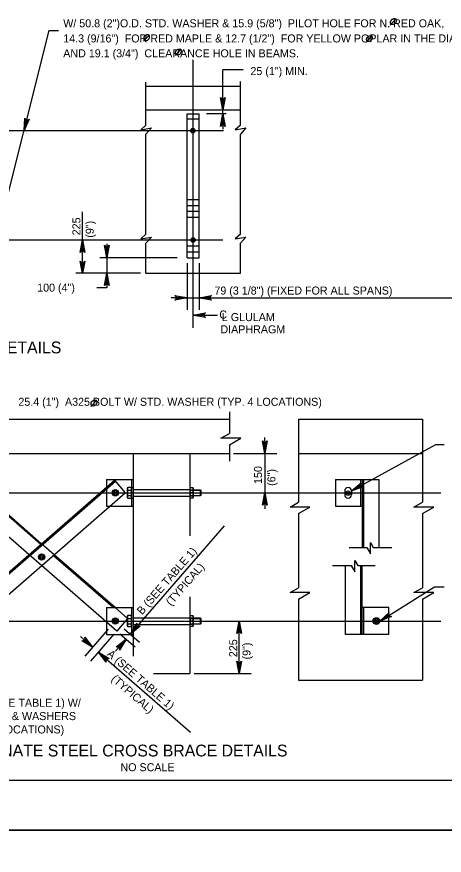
# Model space of a CAD drawing. Extents: x -13 to 81, y -176 to 0.
# Drawn here: x 41.37 to 47.78, y -44.38 to -31.81 of the extents above; entities that cross this region are included whole.
import ezdxf

# ---------------------------------------------------------------- set-up
doc = ezdxf.new("R2010")
doc.units = 0
for name, color, linetype in [('Level 1', 7, 'Continuous'), ('Level 3', 7, 'Continuous'), ('Level 4', 7, 'Continuous'), ('Level 5', 7, 'Continuous'), ('Level 63', 7, 'Continuous'), ('Level 7', 7, 'Continuous'), ('Level 8', 7, 'Continuous')]:
    doc.layers.add(name, color=color, linetype=linetype)

msp = doc.modelspace()

# ---------------------------------------------------------------- linework, layer by layer
at = {"layer": 'Level 1'}
msp.add_lwpolyline([(35.75, -43.25), (67.25, -43.25), (67.25, -22.75), (35.75, -22.75)], close=True, dxfattribs=at)
at = {"layer": 'Level 3'}
for p, q in [((41.07, -35.155), (41.862, -32.017)), ((41.862, -32.017), (41.998, -32.017)), ((44.018, -36.47), (44.018, -32.456)), ((44.767, -32.606), (44.464, -32.606)), ((44.514, -33.267), (44.22, -33.267)), ((37.386, -33.517), (44.475, -33.517)), ((42.361, -35.657), (42.361, -34.732)), ((37.386, -35.155), (44.465, -35.155)), ((42.726, -35.212), (42.726, -35.872)), ((43.777, -35.421), (42.62, -35.421)), ((43.231, -35.653), (42.259, -35.653)), ((42.726, -35.872), (42.577, -35.872)), ((44.018, -36.28), (44.382, -36.28)), ((45.093, -38.354), (45.093, -38.114)), ((44.562, -38.354), (44.562, -38.354)), ((44.624, -38.354), (45.273, -38.354)), ((45.093, -38.354), (45.093, -38.944)), ((44.562, -38.944), (44.562, -38.944)), ((44.624, -38.944), (45.273, -38.944)), ((45.093, -38.944), (45.093, -39.184)), ((45.093, -38.944), (45.093, -38.944)), ((42.718, -39.145), (42.771, -39.145)), ((42.771, -39.145), (43.121, -39.145)), ((43.971, -40.865), (43.971, -40.865)), ((44.034, -40.865), (44.89, -40.865)), ((44.71, -41.653), (44.71, -40.865)), ((44.71, -40.865), (44.71, -40.865)), ((43.971, -41.653), (43.971, -41.653)), ((44.034, -41.653), (44.89, -41.653))]:
    msp.add_line(p, q, dxfattribs=at)
for points in [[(41.483, -33.517), (41.495, -33.328), (41.501, -33.344), (41.511, -33.354), (41.523, -33.359), (41.535, -33.36), (41.549, -33.356), (41.562, -33.345), (41.483, -33.517), (41.549, -33.356), (41.535, -33.36), (41.483, -33.517), (41.523, -33.359), (41.511, -33.354), (41.483, -33.517), (41.501, -33.344)], [(42.361, -35.155), (42.396, -35.341), (42.386, -35.327), (42.374, -35.319), (42.361, -35.317), (42.349, -35.319), (42.336, -35.327), (42.326, -35.341), (42.361, -35.155), (42.336, -35.327), (42.349, -35.319), (42.361, -35.155), (42.361, -35.317), (42.374, -35.319), (42.361, -35.155), (42.386, -35.327)], [(42.726, -35.421), (42.691, -35.234), (42.701, -35.248), (42.713, -35.256), (42.726, -35.258), (42.738, -35.256), (42.751, -35.248), (42.761, -35.234), (42.726, -35.421), (42.751, -35.248), (42.738, -35.256), (42.726, -35.421), (42.726, -35.258), (42.713, -35.256), (42.726, -35.421), (42.701, -35.248)], [(42.361, -35.657), (42.326, -35.471), (42.336, -35.485), (42.349, -35.493), (42.361, -35.495), (42.374, -35.493), (42.386, -35.485), (42.396, -35.471), (42.361, -35.657), (42.386, -35.485), (42.374, -35.493), (42.361, -35.657), (42.361, -35.495), (42.349, -35.493), (42.361, -35.657), (42.336, -35.485)], [(42.726, -35.653), (42.761, -35.839), (42.751, -35.825), (42.738, -35.817), (42.726, -35.815), (42.713, -35.817), (42.701, -35.825), (42.691, -35.839), (42.726, -35.653), (42.701, -35.825), (42.713, -35.817), (42.726, -35.653), (42.726, -35.815), (42.738, -35.817), (42.726, -35.653), (42.751, -35.825)], [(43.929, -36.024), (43.743, -36.059), (43.757, -36.049), (43.765, -36.036), (43.767, -36.024), (43.765, -36.011), (43.757, -35.999), (43.743, -35.989), (43.929, -36.024), (43.757, -35.999), (43.765, -36.011), (43.929, -36.024), (43.767, -36.024), (43.765, -36.036), (43.929, -36.024), (43.757, -36.049)], [(44.107, -36.024), (44.293, -35.989), (44.279, -35.999), (44.271, -36.011), (44.269, -36.024), (44.271, -36.036), (44.279, -36.049), (44.293, -36.059), (44.107, -36.024), (44.279, -36.049), (44.271, -36.036), (44.107, -36.024), (44.269, -36.024), (44.271, -36.011), (44.107, -36.024), (44.279, -35.999)], [(44.018, -36.28), (44.204, -36.245), (44.19, -36.255), (44.183, -36.267), (44.181, -36.28), (44.183, -36.292), (44.19, -36.305), (44.204, -36.315), (44.018, -36.28), (44.19, -36.305), (44.183, -36.292), (44.018, -36.28), (44.181, -36.28), (44.183, -36.267), (44.018, -36.28), (44.19, -36.255)], [(45.093, -38.354), (45.058, -38.167), (45.067, -38.182), (45.08, -38.189), (45.093, -38.191), (45.105, -38.189), (45.117, -38.182), (45.127, -38.167), (45.093, -38.354), (45.117, -38.182), (45.105, -38.189), (45.093, -38.354), (45.093, -38.191), (45.08, -38.189), (45.093, -38.354), (45.067, -38.182)], [(46.392, -38.915), (47.656, -38.218), (47.784, -38.218)], [(45.093, -38.944), (45.127, -39.131), (45.117, -39.116), (45.105, -39.109), (45.093, -39.107), (45.08, -39.109), (45.067, -39.116), (45.057, -39.131), (45.093, -38.944), (45.067, -39.116), (45.08, -39.109), (45.093, -38.944), (45.093, -39.107), (45.105, -39.109), (45.093, -38.944), (45.117, -39.116)], [(46.817, -40.865), (47.64, -40.354), (47.784, -40.354)]]:
    msp.add_lwpolyline(points, dxfattribs=at)
at = {"layer": 'Level 4'}
for p, q in [((46.976, -31.935), (47.065, -31.837)), ((43.275, -32.177), (43.365, -32.079)), ((46.617, -32.191), (46.706, -32.092)), ((43.752, -32.391), (43.841, -32.293)), ((42.486, -37.652), (42.575, -37.554))]:
    msp.add_line(p, q, dxfattribs=at)
for points in [[(47.056, -31.846), (47.049, -31.841), (47.042, -31.839), (47.033, -31.838), (47.028, -31.838), (47.02, -31.84), (47.012, -31.844), (47.006, -31.847), (46.996, -31.855), (46.987, -31.866), (46.982, -31.876), (46.979, -31.886), (46.978, -31.894), (46.979, -31.901), (46.983, -31.912), (46.987, -31.918), (46.994, -31.923), (47.006, -31.926), (47.019, -31.926), (47.036, -31.918), (47.048, -31.908), (47.057, -31.895), (47.063, -31.882), (47.065, -31.867), (47.063, -31.857), (47.056, -31.846)], [(43.355, -32.088), (43.348, -32.083), (43.341, -32.081), (43.333, -32.08), (43.328, -32.08), (43.319, -32.082), (43.311, -32.086), (43.306, -32.089), (43.295, -32.097), (43.287, -32.108), (43.282, -32.118), (43.279, -32.127), (43.278, -32.136), (43.279, -32.143), (43.282, -32.154), (43.286, -32.159), (43.294, -32.165), (43.305, -32.168), (43.319, -32.168), (43.335, -32.16), (43.348, -32.15), (43.357, -32.137), (43.363, -32.124), (43.365, -32.109), (43.362, -32.099), (43.356, -32.088)], [(46.697, -32.102), (46.69, -32.097), (46.683, -32.095), (46.674, -32.094), (46.669, -32.094), (46.661, -32.096), (46.653, -32.1), (46.647, -32.103), (46.637, -32.111), (46.628, -32.122), (46.623, -32.132), (46.62, -32.141), (46.619, -32.15), (46.62, -32.157), (46.624, -32.168), (46.628, -32.173), (46.636, -32.179), (46.647, -32.182), (46.66, -32.181), (46.677, -32.174), (46.689, -32.163), (46.698, -32.151), (46.704, -32.137), (46.706, -32.123), (46.704, -32.113), (46.697, -32.102)], [(43.832, -32.303), (43.825, -32.297), (43.818, -32.295), (43.809, -32.294), (43.804, -32.294), (43.795, -32.296), (43.787, -32.3), (43.782, -32.303), (43.771, -32.312), (43.763, -32.322), (43.758, -32.332), (43.755, -32.342), (43.754, -32.35), (43.755, -32.358), (43.759, -32.368), (43.763, -32.374), (43.77, -32.38), (43.782, -32.382), (43.795, -32.382), (43.812, -32.374), (43.824, -32.364), (43.833, -32.351), (43.839, -32.338), (43.841, -32.323), (43.839, -32.314), (43.832, -32.303)], [(42.566, -37.563), (42.559, -37.558), (42.552, -37.556), (42.543, -37.555), (42.538, -37.555), (42.53, -37.557), (42.522, -37.561), (42.516, -37.564), (42.506, -37.573), (42.497, -37.583), (42.492, -37.593), (42.489, -37.603), (42.488, -37.611), (42.489, -37.619), (42.493, -37.629), (42.497, -37.635), (42.504, -37.641), (42.516, -37.643), (42.529, -37.643), (42.546, -37.635), (42.558, -37.625), (42.567, -37.612), (42.573, -37.599), (42.575, -37.584), (42.573, -37.575), (42.566, -37.563)]]:
    msp.add_spline(points, degree=3, dxfattribs=at)
at = {"layer": 'Level 5'}
for p, q in [((44.464, -32.979), (44.464, -32.606)), ((43.309, -33.436), (43.309, -32.79)), ((44.727, -33.436), (44.727, -32.781)), ((43.309, -32.852), (44.727, -32.852)), ((44.464, -33.267), (44.464, -32.979)), ((43.309, -33.206), (44.727, -33.206)), ((43.929, -35.421), (43.929, -33.267)), ((43.929, -33.267), (44.107, -33.267)), ((44.107, -35.421), (44.107, -33.267)), ((44.464, -33.267), (44.464, -33.494)), ((43.309, -33.436), (43.233, -33.505)), ((43.233, -33.505), (43.393, -33.477)), ((43.393, -33.477), (43.309, -33.568)), ((44.727, -33.436), (44.65, -33.505)), ((44.65, -33.505), (44.811, -33.477)), ((44.811, -33.477), (44.727, -33.568)), ((43.309, -35.069), (43.309, -33.568)), ((44.727, -35.069), (44.727, -33.568)), ((44.727, -34.796), (44.727, -33.568)), ((43.309, -35.069), (43.233, -35.139)), ((43.233, -35.139), (43.393, -35.111)), ((43.393, -35.111), (43.309, -35.201)), ((44.727, -35.069), (44.65, -35.139)), ((44.65, -35.139), (44.811, -35.111)), ((44.811, -35.111), (44.727, -35.201)), ((43.309, -35.653), (43.309, -35.201)), ((44.727, -35.653), (44.727, -35.201)), ((43.929, -35.421), (44.107, -35.421)), ((43.309, -35.653), (44.727, -35.653)), ((44.562, -37.731), (44.562, -38.053)), ((38.932, -37.842), (44.562, -37.842)), ((45.6, -37.842), (45.6, -39.084)), ((45.6, -37.842), (47.456, -37.842)), ((47.456, -37.842), (47.456, -39.084)), ((44.434, -38.127), (44.562, -38.053)), ((44.732, -38.127), (44.434, -38.127)), ((44.562, -38.225), (44.732, -38.127)), ((44.562, -38.225), (44.562, -38.47)), ((38.932, -38.354), (44.562, -38.354)), ((43.121, -38.354), (43.121, -41.391)), ((43.971, -38.354), (43.971, -39.59)), ((45.6, -38.354), (47.456, -38.354)), ((40.458, -40.828), (42.84, -38.756)), ((40.471, -40.842), (42.853, -38.771)), ((42.718, -38.743), (42.718, -38.862)), ((42.718, -38.743), (43.121, -38.743)), ((42.84, -38.756), (43.002, -38.944)), ((43.096, -38.743), (43.096, -39.145)), ((43.121, -38.743), (43.121, -39.145)), ((46.153, -38.743), (46.803, -38.743)), ((46.153, -38.743), (46.153, -39.145)), ((46.531, -38.743), (46.531, -39.145)), ((46.554, -38.743), (46.554, -39.762)), ((46.574, -38.743), (46.574, -39.762)), ((46.803, -38.743), (46.803, -39.762)), ((39.121, -38.944), (44.373, -38.944)), ((40.62, -41.015), (43.002, -38.944)), ((41.747, -39.707), (40.776, -38.862)), ((41.734, -39.721), (40.776, -38.888)), ((42.718, -38.888), (42.718, -39.145)), ((43.038, -38.862), (43.032, -38.873)), ((43.032, -38.873), (43.032, -39.015)), ((43.093, -38.862), (43.038, -38.862)), ((43.038, -38.903), (43.093, -38.903)), ((43.093, -39.026), (43.093, -38.862)), ((43.093, -38.873), (43.096, -38.873)), ((43.096, -38.865), (43.121, -38.865)), ((43.096, -38.873), (43.096, -39.015)), ((43.096, -38.897), (43.098, -38.897)), ((43.121, -38.894), (43.971, -38.894)), ((44.024, -38.944), (43.965, -38.944)), ((43.977, -38.862), (43.971, -38.873)), ((43.971, -38.873), (43.971, -39.015)), ((43.971, -38.897), (43.971, -38.991)), ((43.971, -38.897), (44.018, -38.897)), ((43.971, -38.897), (44.126, -38.897)), ((43.971, -38.903), (44.126, -38.903)), ((43.977, -38.862), (44.012, -38.862)), ((43.977, -38.903), (44.012, -38.903)), ((44.012, -38.862), (44.018, -38.873)), ((44.018, -38.873), (44.018, -39.015)), ((44.126, -38.897), (44.126, -38.991)), ((44.126, -38.897), (44.133, -38.903)), ((44.133, -38.903), (44.133, -38.985)), ((44.373, -38.944), (47.731, -38.944)), ((46.292, -38.915), (46.292, -38.973)), ((46.392, -38.915), (46.392, -38.973)), ((43.032, -39.015), (43.038, -39.026)), ((43.038, -38.985), (43.093, -38.985)), ((43.038, -39.026), (43.093, -39.026)), ((43.096, -38.991), (43.098, -38.991)), ((43.096, -39.023), (43.121, -39.023)), ((43.121, -38.994), (43.971, -38.994)), ((43.971, -38.985), (44.126, -38.985)), ((43.971, -38.991), (44.018, -38.991)), ((44.126, -38.991), (43.971, -38.991)), ((43.971, -39.015), (43.977, -39.026)), ((43.977, -38.985), (44.012, -38.985)), ((44.012, -39.026), (43.977, -39.026)), ((44.018, -39.015), (44.012, -39.026)), ((44.133, -38.985), (44.126, -38.991)), ((41.558, -39.871), (40.723, -39.145)), ((45.472, -39.158), (45.6, -39.084)), ((45.771, -39.158), (45.472, -39.158)), ((45.6, -39.256), (45.771, -39.158)), ((46.153, -39.145), (46.554, -39.145)), ((47.328, -39.158), (47.456, -39.084)), ((47.627, -39.158), (47.328, -39.158)), ((47.456, -39.256), (47.627, -39.158)), ((45.6, -39.256), (45.6, -40.366)), ((47.456, -39.256), (47.456, -40.366)), ((46.678, -39.859), (46.678, -39.69)), ((46.678, -39.69), (46.72, -39.762)), ((41.936, -39.871), (41.747, -39.707)), ((46.358, -39.762), (46.622, -39.762)), ((46.622, -39.762), (46.678, -39.859)), ((46.72, -39.762), (46.999, -39.762)), ((41.747, -40.035), (41.558, -39.871)), ((42.819, -40.665), (41.923, -39.886)), ((42.849, -40.665), (41.936, -39.871)), ((42.718, -40.88), (41.747, -40.035)), ((46.11, -40.031), (46.39, -40.031)), ((46.306, -41.066), (46.306, -40.031)), ((46.39, -40.031), (46.445, -40.127)), ((46.445, -39.959), (46.487, -40.031)), ((46.445, -40.127), (46.445, -39.959)), ((46.487, -40.031), (46.751, -40.031)), ((46.535, -41.066), (46.535, -40.031)), ((46.554, -41.066), (46.554, -40.031)), ((45.472, -40.44), (45.6, -40.366)), ((45.771, -40.44), (45.472, -40.44)), ((45.6, -40.538), (45.771, -40.44)), ((47.328, -40.44), (47.456, -40.366)), ((47.627, -40.44), (47.328, -40.44)), ((47.456, -40.538), (47.627, -40.44)), ((43.971, -40.503), (43.971, -41.653)), ((45.6, -40.538), (45.6, -41.751)), ((47.456, -40.538), (47.456, -41.751)), ((42.718, -40.665), (42.718, -41.066)), ((42.718, -40.665), (43.121, -40.665)), ((43.036, -40.828), (42.849, -40.665)), ((43.096, -40.665), (43.096, -41.066)), ((43.121, -40.665), (43.121, -41.066)), ((46.956, -40.665), (46.554, -40.665)), ((46.578, -41.066), (46.578, -40.665)), ((46.956, -41.066), (46.956, -40.665)), ((43.036, -40.828), (42.873, -41.015)), ((43.038, -40.784), (43.032, -40.794)), ((43.032, -40.794), (43.032, -40.936)), ((43.093, -40.784), (43.038, -40.784)), ((43.038, -40.825), (43.093, -40.825)), ((43.093, -40.947), (43.093, -40.784)), ((43.093, -40.795), (43.096, -40.795)), ((43.096, -40.795), (43.096, -40.936)), ((43.096, -40.818), (43.098, -40.818)), ((43.121, -40.815), (43.971, -40.815)), ((43.977, -40.784), (43.971, -40.794)), ((43.971, -40.794), (43.971, -40.936)), ((43.971, -40.818), (43.971, -40.913)), ((43.971, -40.818), (44.018, -40.818)), ((43.971, -40.818), (44.126, -40.818)), ((43.971, -40.825), (44.126, -40.825)), ((43.977, -40.784), (44.012, -40.784)), ((43.977, -40.825), (44.012, -40.825)), ((44.012, -40.784), (44.018, -40.794)), ((44.018, -40.794), (44.018, -40.936)), ((44.126, -40.818), (44.126, -40.913)), ((44.126, -40.818), (44.133, -40.825)), ((44.133, -40.825), (44.133, -40.906)), ((39.121, -40.865), (44.373, -40.865)), ((42.873, -41.015), (42.718, -40.88)), ((43.032, -40.936), (43.038, -40.947)), ((43.038, -40.906), (43.093, -40.906)), ((43.038, -40.947), (43.093, -40.947)), ((43.096, -40.913), (43.098, -40.913)), ((43.121, -40.915), (43.971, -40.915)), ((44.024, -40.865), (43.965, -40.865)), ((43.971, -40.906), (44.126, -40.906)), ((43.971, -40.913), (44.018, -40.913)), ((44.126, -40.913), (43.971, -40.913)), ((43.971, -40.936), (43.977, -40.947)), ((43.977, -40.906), (44.012, -40.906)), ((44.012, -40.947), (43.977, -40.947)), ((44.018, -40.936), (44.012, -40.947)), ((44.133, -40.906), (44.126, -40.913)), ((44.373, -40.865), (47.731, -40.865)), ((42.718, -41.066), (43.121, -41.066)), ((46.956, -41.066), (46.306, -41.066)), ((43.422, -41.653), (43.971, -41.653)), ((45.6, -41.751), (47.456, -41.751))]:
    msp.add_line(p, q, dxfattribs=at)
for points in [[(44.464, -33.206), (44.429, -33.02), (44.439, -33.034), (44.451, -33.041), (44.464, -33.044), (44.476, -33.041), (44.489, -33.034), (44.499, -33.02), (44.464, -33.206), (44.489, -33.034), (44.476, -33.041), (44.464, -33.206), (44.464, -33.044), (44.451, -33.041), (44.464, -33.206), (44.439, -33.034)], [(44.464, -33.267), (44.499, -33.453), (44.489, -33.439), (44.476, -33.431), (44.464, -33.429), (44.451, -33.431), (44.439, -33.439), (44.429, -33.453), (44.464, -33.267), (44.439, -33.439), (44.451, -33.431), (44.464, -33.267), (44.464, -33.429), (44.476, -33.431), (44.464, -33.267), (44.489, -33.439)]]:
    msp.add_lwpolyline(points, dxfattribs=at)
for centre, radius in [((44.014, -33.517), 0.0333), ((44.014, -33.517), 0.0167), ((44.018, -35.155), 0.0333), ((44.018, -35.155), 0.0167), ((42.852, -38.944), 0.0472), ((42.852, -38.944), 0.0333), ((42.852, -38.944), 0.0167), ((46.341, -38.949), 0.0333), ((46.341, -38.949), 0.0167), ((41.747, -39.905), 0.0472), ((41.747, -39.905), 0.0333), ((41.747, -39.905), 0.0167), ((42.852, -40.865), 0.0472), ((42.852, -40.865), 0.0333), ((46.767, -40.865), 0.05), ((46.767, -40.865), 0.0333), ((42.852, -40.865), 0.0167), ((46.767, -40.865), 0.0167)]:
    msp.add_circle(centre, radius, dxfattribs=at)
for centre, radius, start, end in [((43.069, -38.883), 0.0366, 146, 214), ((43.169, -38.944), 0.137, 162.6175, 197.3825), ((44.008, -38.883), 0.0366, 146, 214), ((44.108, -38.944), 0.137, 162.6175, 197.3825), ((43.982, -38.883), 0.0366, 326, 34), ((43.882, -38.944), 0.137, 342.6175, 17.3825), ((46.342, -38.915), 0.05, 0, 180), ((43.069, -39.006), 0.0366, 146, 214), ((44.008, -39.006), 0.0366, 146, 214), ((43.982, -39.006), 0.0366, 326, 34), ((46.342, -38.973), 0.05, 180, 0), ((43.069, -40.804), 0.0366, 146, 214), ((43.169, -40.865), 0.137, 162.6175, 197.3825), ((44.008, -40.804), 0.0366, 146, 214), ((44.108, -40.865), 0.137, 162.6175, 197.3825), ((43.982, -40.804), 0.0366, 326, 34), ((43.882, -40.865), 0.137, 342.6175, 17.3825), ((43.069, -40.927), 0.0366, 146, 214), ((44.008, -40.927), 0.0366, 146, 214), ((43.982, -40.927), 0.0366, 326, 34)]:
    msp.add_arc(centre, radius, start, end, dxfattribs=at)
at = {"layer": 'Level 63'}
for points in [[(34, -44), (68, -44), (68, -22), (34, -22)], [(34, -66), (68, -66), (68, -44), (34, -44)]]:
    msp.add_lwpolyline(points, close=True, dxfattribs=at)
at = {"layer": 'Level 7'}
for p, q in [((43.929, -33.34), (44.107, -33.34)), ((43.929, -34.548), (44.107, -34.548)), ((43.929, -34.637), (44.107, -34.637)), ((43.929, -34.725), (44.107, -34.725)), ((43.929, -34.814), (44.107, -34.814)), ((43.929, -35.243), (44.107, -35.243)), ((43.929, -35.332), (44.107, -35.332))]:
    msp.add_line(p, q, dxfattribs=at)
at = {"layer": 'Level 8'}
for p, q in [((43.929, -35.503), (43.929, -36.204)), ((44.107, -35.503), (44.107, -36.204)), ((43.929, -36.024), (43.689, -36.024)), ((43.929, -36.024), (44.107, -36.024)), ((44.107, -36.024), (47.935, -36.024)), ((44.624, -38.944), (45.178, -38.944)), ((43.078, -41.062), (44.49, -39.437)), ((44.034, -40.865), (44.75, -40.865)), ((42.746, -40.987), (42.394, -41.392)), ((42.832, -41.062), (42.48, -41.467)), ((42.92, -41.056), (43.149, -41.254)), ((42.985, -40.981), (43.214, -41.18)), ((42.512, -41.257), (42.331, -41.099)), ((43.013, -41.136), (42.856, -41.317)), ((42.598, -41.331), (43.978, -42.531))]:
    msp.add_line(p, q, dxfattribs=at)
for points in [[(46.392, -38.915), (46.538, -38.795), (46.53, -38.81), (46.53, -38.825), (46.534, -38.837), (46.542, -38.847), (46.555, -38.854), (46.572, -38.856), (46.392, -38.915), (46.555, -38.854), (46.542, -38.847), (46.392, -38.915), (46.534, -38.837), (46.53, -38.825), (46.392, -38.915), (46.53, -38.81)], [(46.817, -40.865), (46.957, -40.737), (46.95, -40.753), (46.95, -40.768), (46.955, -40.78), (46.963, -40.789), (46.976, -40.796), (46.994, -40.797), (46.817, -40.865), (46.976, -40.796), (46.963, -40.789), (46.817, -40.865), (46.955, -40.78), (46.95, -40.768), (46.817, -40.865), (46.95, -40.753)], [(43.078, -41.062), (43.174, -40.898), (43.172, -40.916), (43.176, -40.93), (43.184, -40.939), (43.195, -40.946), (43.21, -40.949), (43.227, -40.944), (43.078, -41.062), (43.21, -40.949), (43.195, -40.946), (43.078, -41.062), (43.184, -40.939), (43.176, -40.93), (43.078, -41.062), (43.172, -40.916)], [(44.71, -40.865), (44.745, -41.052), (44.735, -41.038), (44.723, -41.03), (44.71, -41.028), (44.698, -41.03), (44.685, -41.038), (44.675, -41.052), (44.71, -40.865), (44.685, -41.038), (44.698, -41.03), (44.71, -40.865), (44.71, -41.028), (44.723, -41.03), (44.71, -40.865), (44.735, -41.038)], [(42.512, -41.257), (42.348, -41.161), (42.366, -41.163), (42.379, -41.158), (42.389, -41.15), (42.396, -41.139), (42.398, -41.125), (42.394, -41.108), (42.512, -41.257), (42.398, -41.125), (42.396, -41.139), (42.512, -41.257), (42.389, -41.15), (42.379, -41.158), (42.512, -41.257), (42.366, -41.163)], [(43.013, -41.136), (42.917, -41.3), (42.919, -41.283), (42.915, -41.269), (42.907, -41.259), (42.896, -41.252), (42.882, -41.25), (42.865, -41.254), (43.013, -41.136), (42.882, -41.25), (42.896, -41.252), (43.013, -41.136), (42.907, -41.259), (42.915, -41.269), (43.013, -41.136), (42.919, -41.283)], [(42.598, -41.331), (42.762, -41.427), (42.744, -41.425), (42.73, -41.43), (42.721, -41.438), (42.714, -41.449), (42.711, -41.463), (42.716, -41.48), (42.598, -41.331), (42.711, -41.463), (42.714, -41.449), (42.598, -41.331), (42.721, -41.438), (42.73, -41.43), (42.598, -41.331), (42.744, -41.425)], [(44.71, -41.653), (44.675, -41.466), (44.685, -41.481), (44.698, -41.488), (44.71, -41.49), (44.723, -41.488), (44.735, -41.481), (44.745, -41.466), (44.71, -41.653), (44.735, -41.481), (44.723, -41.488), (44.71, -41.653), (44.71, -41.49), (44.698, -41.488), (44.71, -41.653), (44.685, -41.481)]]:
    msp.add_lwpolyline(points, dxfattribs=at)

# ---------------------------------------------------------------- texts
at = {"layer": 'Level 3'}
for s, height, p in [('W/ 50.8 (2")O.D. STD. WASHER & 15.9 (5/8")  PILOT HOLE FOR N. RED OAK, ', 0.12, (42.071, -31.968)), ('14.3 (9/16")  FOR RED MAPLE & 12.7 (1/2")  FOR YELLOW POPLAR IN THE DIAPHRAGM, ', 0.12, (42.071, -32.195)), ('AND 19.1 (3/4")  CLEARANCE HOLE IN BEAMS.', 0.12, (42.071, -32.418)), ('25 (1") MIN.', 0.12, (44.878, -32.684)), ('100 (4")', 0.12, (41.68, -35.929)), ('79 (3 1/8") (FIXED FOR ALL SPANS)', 0.12, (44.338, -35.973)), ('C', 0.12, (44.411, -36.332)), ('L GLULAM', 0.12, (44.45, -36.371)), ('DIAPHRAGM', 0.12, (44.428, -36.554)), ('DIAPHRAGM DETAILS', 0.17717, (39.554, -36.854)), ('25.4 (1")  A325 BOLT W/ STD. WASHER (TYP. 4 LOCATIONS)', 0.12, (41.398, -37.64)), ('BOLT (SEE TABLE 1) W/', 0.12, (40.516, -42.15)), ('STD. NUT & WASHERS', 0.12, (40.516, -42.35)), ('(TYP. 5 LOCATIONS)', 0.12, (40.516, -42.55)), ('ALTERNATE STEEL CROSS BRACE DETAILS', 0.17717, (40.378, -42.895)), ('NO SCALE', 0.12, (42.929, -43.116))]:
    msp.add_text(s, height=height, dxfattribs=at).set_placement(p)
for s, p in [('225', (42.328, -35.086)), ('(9")', (42.528, -35.121)), ('150', (45.052, -38.811)), ('(6")', (45.252, -38.84)), ('225', (44.68, -41.407)), ('(9")', (44.88, -41.441))]:
    msp.add_text(s, height=0.12, rotation=90, dxfattribs=at).set_placement(p)
at = {"layer": 'Level 8'}
for s, rotation, p in [(' B (SEE TABLE 1)', 48.9947, (43.224, -40.814)), ('(TYPICAL)', 48.9947, (43.688, -40.646)), (' A (SEE TABLE 1)', 318.996, (42.683, -41.345)), ('(TYPICAL)', 318.996, (42.78, -41.748))]:
    msp.add_text(s, height=0.12, rotation=rotation, dxfattribs=at).set_placement(p)

doc.saveas('drawing.dxf')
